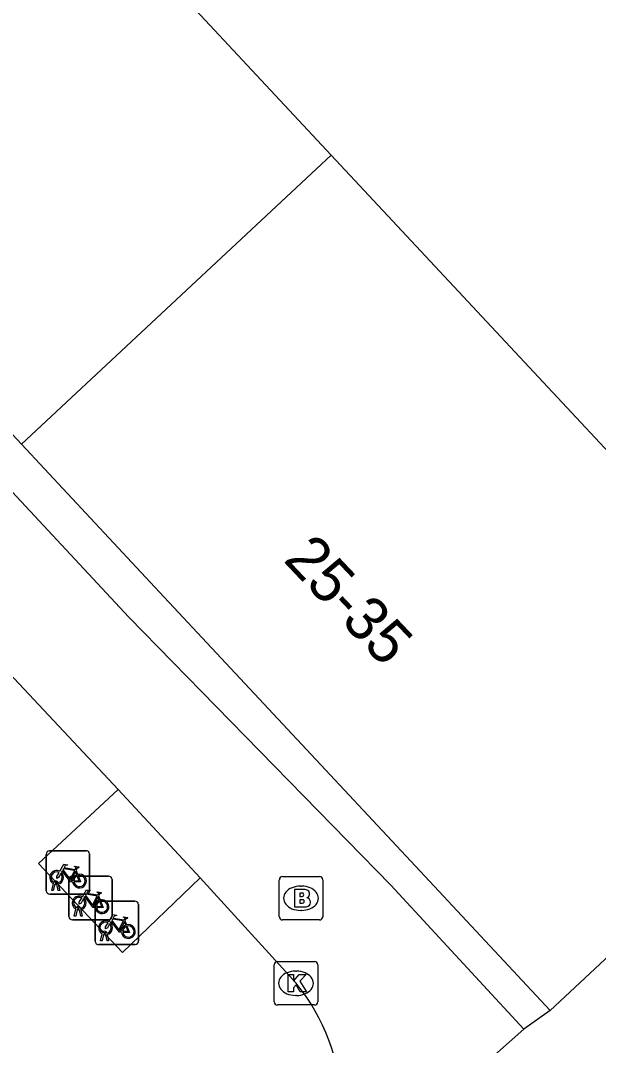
# Model space of a CAD drawing. Extents: x 162347 to 162868, y 381221 to 381813.
# Drawn here: x 162647.04 to 162660.36, y 381549.72 to 381573.33 of the extents above; entities that cross this region are included whole.
import ezdxf

# ---------------------------------------------------------------- set-up
doc = ezdxf.new("R2010")
doc.units = 0
for name, color, linetype in [('IMGEO_Brandkraan', 7, 'Continuous'), ('IMGEO_Fietsenrek', 7, 'Continuous'), ('IMGEO_Kolk', 7, 'Continuous'), ('IMGEO_Pand', 7, 'Continuous'), ('IMGEO_Pand_nummerreeks', 7, 'Continuous'), ('IMGEO_Voetpad_open', 7, 'Continuous')]:
    doc.layers.add(name, color=color, linetype=linetype)

msp = doc.modelspace()

# ---------------------------------------------------------------- linework, layer by layer
at = {"layer": 'IMGEO_Brandkraan'}
for p, q in [((162653.007, 381552.682), (162653.007, 381553.534)), ((162653.082, 381553.608), (162653.934, 381553.608)), ((162654.008, 381553.534), (162654.008, 381552.682)), ((162653.495, 381553.388), (162653.52, 381553.388)), ((162653.518, 381552.828), (162653.493, 381552.828)), ((162653.934, 381552.608), (162653.082, 381552.608))]:
    msp.add_line(p, q, dxfattribs=at)
for points in [[(162653.007, 381552.682), (162653.007, 381553.534)], [(162653.082, 381553.608), (162653.934, 381553.608)], [(162654.008, 381553.534), (162654.008, 381552.682)], [(162653.355, 381553.308), (162653.355, 381552.908), (162653.568, 381552.908)], [(162653.586, 381553.308), (162653.355, 381553.308)], [(162653.534, 381553.227), (162653.48, 381553.227), (162653.48, 381553.151)], [(162653.48, 381553.151), (162653.533, 381553.151)], [(162653.542, 381553.075), (162653.48, 381553.075), (162653.48, 381552.994)], [(162653.48, 381552.994), (162653.542, 381552.994)], [(162653.934, 381552.608), (162653.082, 381552.608)]]:
    msp.add_lwpolyline(points, dxfattribs=at)
for centre, radius, start, end in [((162653.084, 381553.532), 0.0765, 91.552, 178.448), ((162653.084, 381553.532), 0.0765, 91.552, 178.448), ((162653.932, 381553.532), 0.0765, 1.552, 88.448), ((162653.932, 381553.532), 0.0765, 1.552, 88.448), ((162653.59, 381553.163), 0.145, 59.4692, 91.5367), ((162653.615, 381553.21), 0.0922, 285.5137, 58.1501), ((162653.535, 381553.189), 0.0379, 267.8285, 90.9355), ((162653.543, 381553.034), 0.0404, 269.8759, 90.5077), ((162653.62, 381553.018), 0.105, 301.3115, 78.989), ((162653.574, 381553.159), 0.251, 268.6676, 293.5347), ((162653.084, 381552.684), 0.0765, 181.552, 268.448), ((162653.084, 381552.684), 0.0765, 181.552, 268.448), ((162653.932, 381552.684), 0.0765, 271.552, 358.448), ((162653.932, 381552.684), 0.0765, 271.552, 358.448)]:
    msp.add_arc(centre, radius, start, end, dxfattribs=at)
for centre, major_axis, ratio, start_param, end_param in [((162653.494, 381553.108), (-0.387, 0.002), 0.722429, 4.712389, 7.853982), ((162653.519, 381553.108), (-0.39, 0.002), 0.717154, 1.570796, 4.712389)]:
    msp.add_ellipse(centre, major_axis=major_axis, ratio=ratio, start_param=start_param, end_param=end_param, dxfattribs=at)
at = {"layer": 'IMGEO_Fietsenrek'}
for p, q in [((162647.711, 381554.203), (162648.552, 381554.203)), ((162648.552, 381554.203), (162647.711, 381554.203)), ((162647.636, 381553.278), (162647.636, 381554.119)), ((162647.636, 381554.119), (162647.636, 381553.278)), ((162648.636, 381554.128), (162648.636, 381553.287)), ((162648.636, 381553.287), (162648.636, 381554.128)), ((162648.323, 381553.752), (162648.359, 381553.657)), ((162648.156, 381552.689), (162648.156, 381553.53)), ((162648.156, 381553.53), (162648.156, 381552.689)), ((162648.231, 381553.614), (162649.072, 381553.614)), ((162649.072, 381553.614), (162648.231, 381553.614)), ((162649.156, 381553.539), (162649.156, 381552.698)), ((162649.156, 381552.698), (162649.156, 381553.539)), ((162647.763, 381553.287), (162647.802, 381553.447)), ((162647.797, 381553.287), (162647.763, 381553.287)), ((162647.832, 381553.435), (162647.797, 381553.287)), ((162647.874, 381553.459), (162647.873, 381553.463)), ((162647.915, 381553.287), (162647.881, 381553.429)), ((162647.905, 381553.47), (162647.906, 381553.463)), ((162647.913, 381553.433), (162647.948, 381553.287)), ((162647.948, 381553.287), (162647.915, 381553.287)), ((162648.561, 381553.203), (162647.72, 381553.203)), ((162647.72, 381553.203), (162648.561, 381553.203)), ((162648.838, 381553.041), (162649.679, 381553.041)), ((162649.679, 381553.041), (162648.838, 381553.041)), ((162648.843, 381553.163), (162648.879, 381553.068)), ((162648.283, 381552.698), (162648.322, 381552.858)), ((162648.352, 381552.846), (162648.317, 381552.698)), ((162648.394, 381552.87), (162648.393, 381552.874)), ((162648.435, 381552.698), (162648.401, 381552.84)), ((162648.425, 381552.881), (162648.426, 381552.874)), ((162648.433, 381552.844), (162648.468, 381552.698)), ((162648.763, 381552.116), (162648.763, 381552.957)), ((162648.763, 381552.957), (162648.763, 381552.116)), ((162649.763, 381552.966), (162649.763, 381552.125)), ((162649.763, 381552.125), (162649.763, 381552.966)), ((162649.081, 381552.614), (162648.24, 381552.614)), ((162648.24, 381552.614), (162649.081, 381552.614)), ((162648.317, 381552.698), (162648.283, 381552.698)), ((162648.468, 381552.698), (162648.435, 381552.698)), ((162649.45, 381552.59), (162649.486, 381552.495)), ((162649.001, 381552.297), (162649, 381552.301)), ((162649.032, 381552.308), (162649.033, 381552.301)), ((162648.89, 381552.125), (162648.929, 381552.285)), ((162648.924, 381552.125), (162648.89, 381552.125)), ((162648.959, 381552.273), (162648.924, 381552.125)), ((162649.042, 381552.125), (162649.008, 381552.267)), ((162649.04, 381552.271), (162649.075, 381552.125)), ((162649.075, 381552.125), (162649.042, 381552.125)), ((162649.688, 381552.041), (162648.847, 381552.041)), ((162648.847, 381552.041), (162649.688, 381552.041))]:
    msp.add_line(p, q, dxfattribs=at)
for points in [[(162647.949, 381553.729), (162648.044, 381553.893), (162648.13, 381553.879), (162648.132, 381553.87), (162648.076, 381553.859), (162648.049, 381553.814), (162648.305, 381553.773)], [(162648.245, 381553.485), (162648.195, 381553.485), (162648.004, 381553.736), (162647.985, 381553.704)], [(162648.292, 381553.748), (162648.035, 381553.789), (162648.018, 381553.76), (162648.185, 381553.54), (162648.292, 381553.748)], [(162648.34, 381553.65), (162648.31, 381553.727), (162648.201, 381553.509), (162648.244, 381553.509)], [(162648.305, 381553.773), (162648.33, 381553.822), (162648.324, 381553.826), (162648.301, 381553.83), (162648.289, 381553.837), (162648.288, 381553.84), (162648.29, 381553.845), (162648.385, 381553.83), (162648.387, 381553.82), (162648.377, 381553.807), (162648.365, 381553.801), (162648.351, 381553.807), (162648.323, 381553.752)], [(162647.97, 381553.677), (162647.918, 381553.587), (162647.878, 381553.562), (162647.879, 381553.609), (162647.934, 381553.703)], [(162648.274, 381553.509), (162648.394, 381553.508), (162648.35, 381553.622)], [(162648.37, 381553.629), (162648.425, 381553.484), (162648.275, 381553.484)], [(162648.469, 381553.14), (162648.564, 381553.304), (162648.65, 381553.29), (162648.652, 381553.281), (162648.596, 381553.27), (162648.569, 381553.225), (162648.825, 381553.184)], [(162648.825, 381553.184), (162648.85, 381553.233), (162648.844, 381553.237), (162648.821, 381553.241), (162648.809, 381553.248), (162648.808, 381553.251), (162648.81, 381553.256), (162648.905, 381553.241), (162648.907, 381553.231), (162648.897, 381553.218), (162648.885, 381553.212), (162648.871, 381553.218), (162648.843, 381553.163)], [(162648.49, 381553.088), (162648.438, 381552.998), (162648.398, 381552.973), (162648.399, 381553.02), (162648.454, 381553.114)], [(162648.765, 381552.896), (162648.715, 381552.896), (162648.524, 381553.147), (162648.505, 381553.115)], [(162648.812, 381553.159), (162648.555, 381553.2), (162648.538, 381553.171), (162648.705, 381552.951), (162648.812, 381553.159)], [(162648.86, 381553.061), (162648.83, 381553.138), (162648.721, 381552.92), (162648.764, 381552.92)], [(162648.794, 381552.92), (162648.914, 381552.919), (162648.87, 381553.033)], [(162648.89, 381553.04), (162648.945, 381552.895), (162648.795, 381552.895)], [(162649.097, 381552.515), (162649.045, 381552.425), (162649.005, 381552.4), (162649.006, 381552.447), (162649.061, 381552.541)], [(162649.076, 381552.567), (162649.171, 381552.731), (162649.257, 381552.717), (162649.259, 381552.708), (162649.203, 381552.697), (162649.176, 381552.652), (162649.432, 381552.611)], [(162649.372, 381552.323), (162649.322, 381552.323), (162649.131, 381552.574), (162649.112, 381552.542)], [(162649.419, 381552.586), (162649.162, 381552.627), (162649.145, 381552.598), (162649.312, 381552.378), (162649.419, 381552.586)], [(162649.467, 381552.488), (162649.437, 381552.565), (162649.328, 381552.347), (162649.371, 381552.347)], [(162649.432, 381552.611), (162649.457, 381552.66), (162649.451, 381552.664), (162649.428, 381552.668), (162649.416, 381552.675), (162649.415, 381552.678), (162649.417, 381552.683), (162649.512, 381552.668), (162649.514, 381552.658), (162649.504, 381552.645), (162649.492, 381552.639), (162649.478, 381552.645), (162649.45, 381552.59)], [(162649.401, 381552.347), (162649.521, 381552.346), (162649.477, 381552.46)], [(162649.497, 381552.467), (162649.552, 381552.322), (162649.402, 381552.322)]]:
    msp.add_lwpolyline(points, dxfattribs=at)
for centre, radius, start, end in [((162647.714, 381554.125), 0.0779, 92.4484, 184.2845), ((162647.714, 381554.125), 0.0779, 92.4484, 184.2845), ((162648.558, 381554.125), 0.0779, 2.4484, 94.2845), ((162648.558, 381554.125), 0.0779, 2.4484, 94.2845), ((162647.876, 381553.588), 0.159, 62.6766, 242.1369), ((162647.876, 381553.588), 0.129, 63.3192, 238.903), ((162647.856, 381553.459), 0.0499, 12.8025, 158.6934), ((162647.876, 381553.588), 0.129, 283.6043, 43.4302), ((162647.876, 381553.588), 0.159, 283.5766, 46.6042), ((162648.234, 381553.536), 0.0779, 92.4484, 184.2845), ((162648.234, 381553.536), 0.0779, 92.4484, 184.2845), ((162648.403, 381553.504), 0.159, 113.3408, 178.3217), ((162648.403, 381553.504), 0.159, 187.0065, 105.7708), ((162648.403, 381553.504), 0.129, 113.923, 177.9556), ((162648.403, 381553.504), 0.129, 188.6715, 104.5883), ((162649.078, 381553.536), 0.0779, 2.4484, 94.2845), ((162649.078, 381553.536), 0.0779, 2.4484, 94.2845), ((162647.714, 381553.281), 0.0779, 182.4484, 274.2845), ((162647.714, 381553.281), 0.0779, 182.4484, 274.2845), ((162647.876, 381553.588), 0.159, 253.9967, 271.7867), ((162647.856, 381553.459), 0.0174, 12.8025, 163.4502), ((162647.876, 381553.588), 0.129, 253.415, 269.0204), ((162648.558, 381553.281), 0.0779, 272.4484, 4.2845), ((162648.558, 381553.281), 0.0779, 272.4484, 4.2845), ((162648.396, 381552.999), 0.159, 62.6766, 242.1369), ((162648.396, 381552.999), 0.129, 63.3192, 238.903), ((162648.396, 381552.999), 0.129, 283.6043, 43.4302), ((162648.396, 381552.999), 0.159, 283.5766, 46.6042), ((162648.841, 381552.963), 0.0779, 92.4484, 184.2845), ((162648.841, 381552.963), 0.0779, 92.4484, 184.2845), ((162648.923, 381552.915), 0.159, 113.3408, 178.3217), ((162648.923, 381552.915), 0.159, 187.0065, 105.7708), ((162648.923, 381552.915), 0.129, 113.923, 177.9556), ((162648.923, 381552.915), 0.129, 188.6715, 104.5883), ((162649.685, 381552.963), 0.0779, 2.4484, 94.2845), ((162649.685, 381552.963), 0.0779, 2.4484, 94.2845), ((162648.376, 381552.87), 0.0499, 12.8025, 158.6934), ((162648.396, 381552.999), 0.159, 253.9967, 271.7867), ((162648.376, 381552.87), 0.0174, 12.8025, 163.4502), ((162648.396, 381552.999), 0.129, 253.415, 269.0204), ((162648.234, 381552.692), 0.0779, 182.4484, 274.2845), ((162648.234, 381552.692), 0.0779, 182.4484, 274.2845), ((162649.003, 381552.426), 0.159, 62.6766, 242.1369), ((162649.003, 381552.426), 0.129, 63.3192, 238.903), ((162649.003, 381552.426), 0.159, 283.5766, 46.6042), ((162649.078, 381552.692), 0.0779, 272.4484, 4.2845), ((162649.078, 381552.692), 0.0779, 272.4484, 4.2845), ((162648.983, 381552.297), 0.0499, 12.8025, 158.6934), ((162648.983, 381552.297), 0.0174, 12.8025, 163.4502), ((162649.003, 381552.426), 0.129, 253.415, 269.0204), ((162649.003, 381552.426), 0.129, 283.6043, 43.4302), ((162649.53, 381552.342), 0.159, 113.3408, 178.3217), ((162649.53, 381552.342), 0.159, 187.0065, 105.7708), ((162649.53, 381552.342), 0.129, 113.923, 177.9556), ((162649.53, 381552.342), 0.129, 188.6715, 104.5883), ((162648.841, 381552.119), 0.0779, 182.4484, 274.2845), ((162648.841, 381552.119), 0.0779, 182.4484, 274.2845), ((162649.003, 381552.426), 0.159, 253.9967, 271.7867), ((162649.685, 381552.119), 0.0779, 272.4484, 4.2845), ((162649.685, 381552.119), 0.0779, 272.4484, 4.2845)]:
    msp.add_arc(centre, radius, start, end, dxfattribs=at)
at = {"layer": 'IMGEO_Kolk'}
for p, q in [((162652.966, 381551.649), (162653.818, 381551.649)), ((162652.891, 381550.723), (162652.891, 381551.575)), ((162653.379, 381551.429), (162653.404, 381551.429)), ((162653.892, 381551.575), (162653.892, 381550.723)), ((162653.818, 381550.649), (162652.966, 381550.649)), ((162653.402, 381550.869), (162653.377, 381550.869))]:
    msp.add_line(p, q, dxfattribs=at)
for points in [[(162652.966, 381551.649), (162653.818, 381551.649)], [(162652.891, 381550.723), (162652.891, 381551.575)], [(162653.892, 381551.575), (162653.892, 381550.723)], [(162653.212, 381551.349), (162653.335, 381551.349), (162653.335, 381551.198), (162653.465, 381551.349), (162653.629, 381551.349), (162653.483, 381551.198), (162653.636, 381550.949), (162653.484, 381550.949), (162653.399, 381551.113), (162653.335, 381551.046), (162653.335, 381550.949), (162653.212, 381550.949), (162653.212, 381551.349)], [(162653.818, 381550.649), (162652.966, 381550.649)]]:
    msp.add_lwpolyline(points, dxfattribs=at)
for centre, start, end in [((162652.968, 381551.573), 91.552, 178.448), ((162652.968, 381551.573), 91.552, 178.448), ((162653.816, 381551.573), 1.552, 88.448), ((162653.816, 381551.573), 1.552, 88.448), ((162652.968, 381550.725), 181.552, 268.448), ((162652.968, 381550.725), 181.552, 268.448), ((162653.816, 381550.725), 271.552, 358.448), ((162653.816, 381550.725), 271.552, 358.448)]:
    msp.add_arc(centre, 0.0765, start, end, dxfattribs=at)
for centre, major_axis, ratio, start_param, end_param in [((162653.378, 381551.149), (-0.387, 0.002), 0.722429, 4.712389, 7.853982), ((162653.403, 381551.149), (-0.39, 0.002), 0.717154, 1.570796, 4.712389)]:
    msp.add_ellipse(centre, major_axis=major_axis, ratio=ratio, start_param=start_param, end_param=end_param, dxfattribs=at)
at = {"layer": 'IMGEO_Pand'}
for points in [[(162642.256, 381583.018), (162654.2, 381570.228)], [(162647.067, 381563.566), (162644.391, 381566.431), (162637.954, 381573.325), (162635.123, 381576.357)], [(162654.2, 381570.228), (162647.067, 381563.566)], [(162666.149, 381557.432), (162666.036, 381557.553), (162654.2, 381570.228)], [(162647.067, 381563.566), (162650.247, 381560.161), (162656.146, 381553.844), (162659.249, 381550.521)], [(162659.249, 381550.521), (162666.382, 381557.182), (162666.149, 381557.432)]]:
    msp.add_lwpolyline(points, dxfattribs=at)
at = {"layer": 'IMGEO_Voetpad_open'}
for points in [[(162658.64, 381550.091), (162655.573, 381553.411), (162649.537, 381559.582), (162643.742, 381565.799), (162637.295, 381572.722), (162631.525, 381578.914), (162625.475, 381585.332), (162622.507, 381588.51)], [(162639.341, 381566.221), (162649.293, 381555.613)], [(162649.293, 381555.613), (162647.46, 381553.909), (162649.397, 381551.86), (162651.181, 381553.575)], [(162649.293, 381555.613), (162651.181, 381553.575)], [(162651.181, 381553.575), (162653.392, 381551.149)], [(162659.249, 381550.521), (162658.64, 381550.091)], [(162653.565, 381545.59), (162658.64, 381550.091)]]:
    msp.add_lwpolyline(points, dxfattribs=at)
msp.add_arc((162649.9, 381548.258), 4.533, 323.9427, 39.6223, dxfattribs=at)

# ---------------------------------------------------------------- texts
at = {"layer": 'IMGEO_Pand_nummerreeks'}
msp.add_text('25-35', height=1, rotation=313.4276, dxfattribs=at).set_placement((162653.079, 381560.886))

doc.saveas('drawing.dxf')
